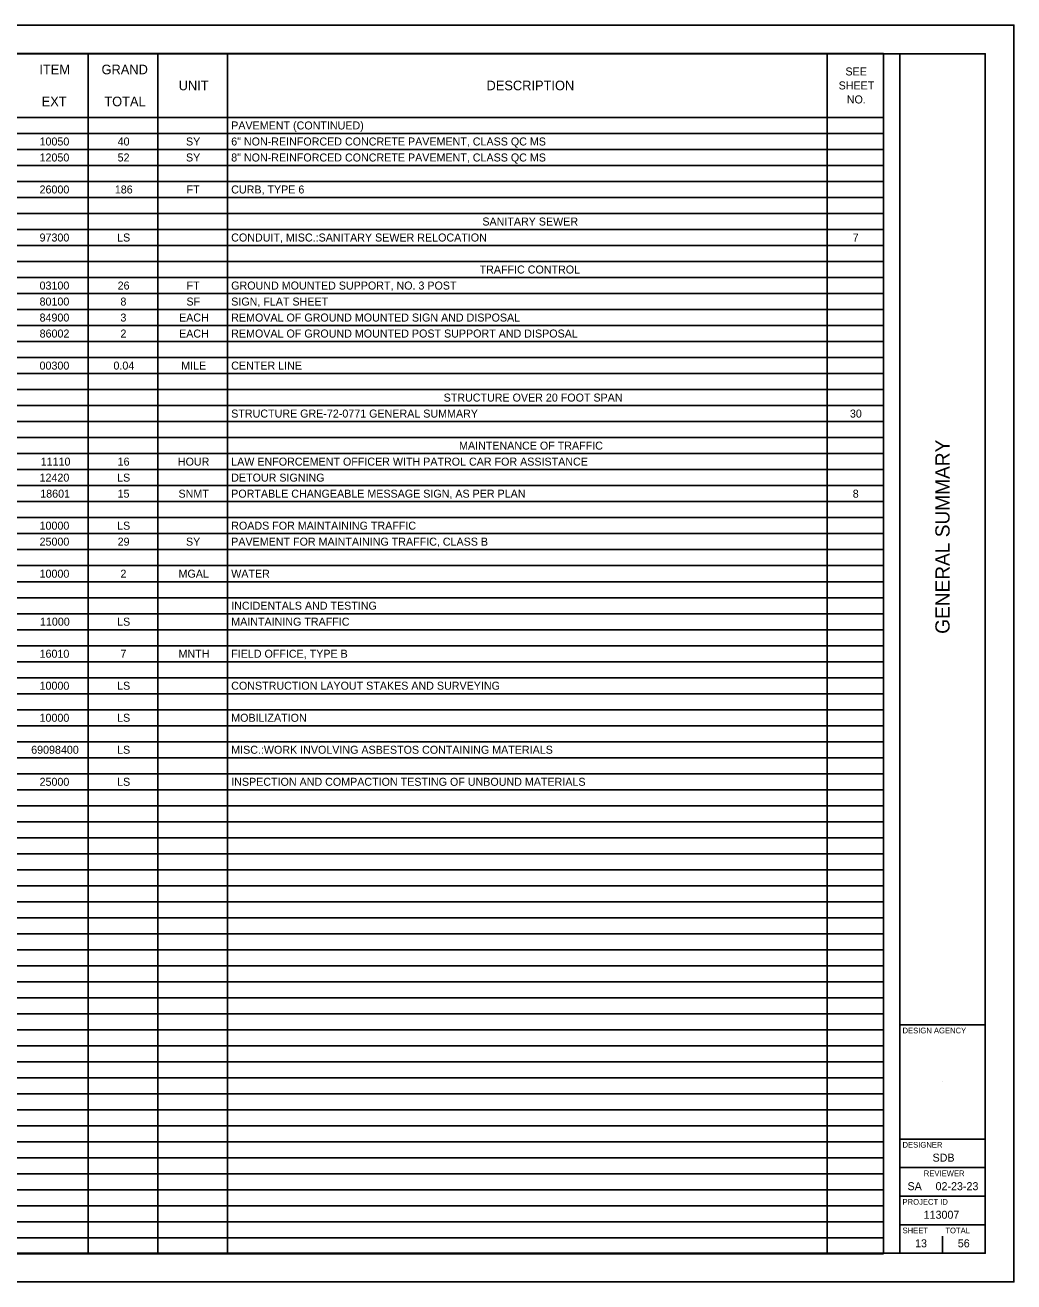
# Model space of a CAD drawing. Extents: x 0 to 34, y 0 to 22.
# Drawn here: x 16.69 to 34, y 0 to 22 of the extents above; entities that cross this region are included whole.
import ezdxf

# ---------------------------------------------------------------- set-up
doc = ezdxf.new("R2010")
doc.units = 0
for name, color, linetype in [('SH_Border', 7, 'Continuous'), ('SH_Cut_Line', 7, 'Continuous'), ('SH_Data', 7, 'Continuous'), ('SH_Text', 7, 'Continuous')]:
    doc.layers.add(name, color=color, linetype=linetype)

msp = doc.modelspace()

# ---------------------------------------------------------------- linework, layer by layer
at = {"layer": 'SH_Border'}
for p, q in [((32, 0.5), (32, 21.5)), ((32, 4.5), (33.5, 4.5)), ((32, 2.5), (33.5, 2.5)), ((32, 2), (33.5, 2)), ((32, 1.5), (33.5, 1.5)), ((32, 1), (33.5, 1))]:
    msp.add_line(p, q, dxfattribs=at)
msp.add_lwpolyline([(1.5, 21.5), (33.5, 21.5), (33.5, 0.5), (1.5, 0.5)], close=True, dxfattribs=at)
at = {"layer": 'SH_Cut_Line'}
msp.add_lwpolyline([(0, 0), (34, 0), (34, 22), (0, 22)], close=True, dxfattribs=at)
at = {"layer": 'SH_Data'}
for p, q in [((32.75, 3.5), (32.75, 3.5)), ((32.375, 0.675), (32.375, 0.675)), ((32.75, 0.5), (32.75, 0.8))]:
    msp.add_line(p, q, dxfattribs=at)
at = {"layer": 'SH_Text'}
for p, q in [((1.503, 21.505), (31.718, 21.505)), ((17.789, 21.505), (17.789, 0.488)), ((19.009, 21.505), (19.009, 0.488)), ((20.228, 21.505), (20.228, 0.488)), ((30.729, 21.505), (30.729, 0.488)), ((31.718, 21.505), (31.718, 0.488)), ((1.503, 20.384), (31.718, 20.384)), ((1.503, 20.104), (31.718, 20.104)), ((1.503, 19.823), (31.718, 19.823)), ((1.503, 19.543), (31.718, 19.543)), ((1.503, 19.263), (31.718, 19.263)), ((1.503, 18.983), (31.718, 18.983)), ((1.503, 18.702), (31.718, 18.702)), ((1.503, 18.422), (31.718, 18.422)), ((1.503, 18.142), (31.718, 18.142)), ((1.503, 17.862), (31.718, 17.862)), ((1.503, 17.582), (31.718, 17.582)), ((1.503, 17.301), (31.718, 17.301)), ((1.503, 17.021), (31.718, 17.021)), ((1.503, 16.741), (31.718, 16.741)), ((1.503, 16.461), (31.718, 16.461)), ((1.503, 16.18), (31.718, 16.18)), ((1.503, 15.9), (31.718, 15.9)), ((1.503, 15.62), (31.718, 15.62)), ((1.503, 15.34), (31.718, 15.34)), ((1.503, 15.06), (31.718, 15.06)), ((1.503, 14.779), (31.718, 14.779)), ((1.503, 14.499), (31.718, 14.499)), ((1.503, 14.219), (31.718, 14.219)), ((1.503, 13.939), (31.718, 13.939)), ((1.503, 13.658), (31.718, 13.658)), ((1.503, 13.378), (31.718, 13.378)), ((1.503, 13.098), (31.718, 13.098)), ((1.503, 12.818), (31.718, 12.818)), ((1.503, 12.538), (31.718, 12.538)), ((1.503, 12.257), (31.718, 12.257)), ((1.503, 11.977), (31.718, 11.977)), ((1.503, 11.697), (31.718, 11.697)), ((1.503, 11.417), (31.718, 11.417)), ((1.503, 11.136), (31.718, 11.136)), ((1.503, 10.856), (31.718, 10.856)), ((1.503, 10.576), (31.718, 10.576)), ((1.503, 10.296), (31.718, 10.296)), ((1.503, 10.016), (31.718, 10.016)), ((1.503, 9.735), (31.718, 9.735)), ((1.503, 9.455), (31.718, 9.455)), ((1.503, 9.175), (31.718, 9.175)), ((1.503, 8.895), (31.718, 8.895)), ((1.503, 8.614), (31.718, 8.614)), ((1.503, 8.334), (31.718, 8.334)), ((1.503, 8.054), (31.718, 8.054)), ((1.503, 7.774), (31.718, 7.774)), ((1.503, 7.494), (31.718, 7.494)), ((1.503, 7.213), (31.718, 7.213)), ((1.503, 6.933), (31.718, 6.933)), ((1.503, 6.653), (31.718, 6.653)), ((1.503, 6.373), (31.718, 6.373)), ((1.503, 6.092), (31.718, 6.092)), ((1.503, 5.812), (31.718, 5.812)), ((1.503, 5.532), (31.718, 5.532)), ((1.503, 5.252), (31.718, 5.252)), ((1.503, 4.972), (31.718, 4.972)), ((1.503, 4.691), (31.718, 4.691)), ((1.503, 4.411), (31.718, 4.411)), ((1.503, 4.131), (31.718, 4.131)), ((1.503, 3.851), (31.718, 3.851)), ((1.503, 3.57), (31.718, 3.57)), ((1.503, 3.29), (31.718, 3.29)), ((1.503, 3.01), (31.718, 3.01)), ((1.503, 2.73), (31.718, 2.73)), ((1.503, 2.45), (31.718, 2.45)), ((1.503, 2.169), (31.718, 2.169)), ((1.503, 1.889), (31.718, 1.889)), ((1.503, 1.609), (31.718, 1.609)), ((1.503, 1.329), (31.718, 1.329)), ((1.503, 1.048), (31.718, 1.048)), ((1.503, 0.768), (31.718, 0.768)), ((1.503, 0.488), (31.718, 0.488))]:
    msp.add_line(p, q, dxfattribs=at)

# ---------------------------------------------------------------- texts
at = {"layer": 'SH_Data'}
msp.add_text('GENERAL SUMMARY', height=0.25, rotation=90, dxfattribs=at).set_placement((32.875, 11.344))
for s, height, p in [('DESIGN AGENCY', 0.1, (32.05, 4.35)), ('DESIGNER', 0.1, (32.05, 2.35)), ('SDB', 0.14, (32.576, 2.105)), ('REVIEWER', 0.1, (32.422, 1.85)), ('SA', 0.14, (32.138, 1.605)), ('02-23-23', 0.14, (32.629, 1.605)), ('PROJECT ID', 0.1, (32.05, 1.35)), ('113007', 0.14, (32.42, 1.105)), ('SHEET', 0.1, (32.05, 0.85)), ('TOTAL', 0.1, (32.8, 0.85)), ('13', 0.14, (32.27, 0.605)), ('56', 0.14, (33.018, 0.605))]:
    msp.add_text(s, height=height, dxfattribs=at).set_placement(p)
at = {"layer": 'SH_Text'}
for s, height, p in [('ITEM', 0.1681, (16.934, 21.14)), ('GRAND', 0.1681, (18.023, 21.14)), ('SEE ', 0.1401, (31.051, 21.119)), ('UNIT', 0.1681, (19.374, 20.86)), ('DESCRIPTION', 0.16814, (24.765, 20.86)), ('SHEET ', 0.1401, (30.931, 20.874)), ('EXT', 0.1681, (16.975, 20.58)), ('TOTAL', 0.1681, (18.072, 20.58)), ('NO.', 0.1401, (31.074, 20.629)), ('PAVEMENT (CONTINUED)', 0.14012, (20.294, 20.174)), ('10050', 0.1401, (16.938, 19.893)), ('40', 0.1401, (18.305, 19.893)), ('SY', 0.1401, (19.502, 19.893)), ('6" NON-REINFORCED CONCRETE PAVEMENT, CLASS QC MS', 0.14012, (20.294, 19.893)), ('12050', 0.1401, (16.938, 19.613)), ('52', 0.1401, (18.305, 19.613)), ('SY', 0.1401, (19.502, 19.613)), ('8" NON-REINFORCED CONCRETE PAVEMENT, CLASS QC MS', 0.14012, (20.294, 19.613)), ('26000', 0.1401, (16.938, 19.053)), ('186', 0.1401, (18.256, 19.053)), ('FT', 0.1401, (19.513, 19.053)), ('CURB, TYPE 6', 0.14012, (20.294, 19.053)), ('SANITARY SEWER', 0.14012, (24.692, 18.492)), ('97300', 0.1401, (16.938, 18.212)), ('LS', 0.1401, (18.296, 18.212)), ('CONDUIT, MISC.:SANITARY SEWER RELOCATION', 0.14012, (20.294, 18.212)), ('7', 0.14, (31.178, 18.212)), ('TRAFFIC CONTROL', 0.14012, (24.644, 17.652)), ('03100', 0.1401, (16.938, 17.371)), ('26', 0.1401, (18.305, 17.371)), ('FT', 0.1401, (19.513, 17.371)), ('GROUND MOUNTED SUPPORT, NO. 3 POST', 0.14012, (20.294, 17.371)), ('80100', 0.1401, (16.938, 17.091)), ('8', 0.14, (18.354, 17.091)), ('SF', 0.1401, (19.51, 17.091)), ('SIGN, FLAT SHEET', 0.14012, (20.294, 17.091)), ('84900', 0.1401, (16.938, 16.811)), ('3', 0.14, (18.354, 16.811)), ('EACH', 0.1401, (19.381, 16.811)), ('REMOVAL OF GROUND MOUNTED SIGN AND DISPOSAL', 0.14012, (20.294, 16.811)), ('86002', 0.1401, (16.939, 16.531)), ('2', 0.14, (18.354, 16.531)), ('EACH', 0.1401, (19.381, 16.531)), ('REMOVAL OF GROUND MOUNTED POST SUPPORT AND DISPOSAL', 0.14012, (20.294, 16.531)), ('00300', 0.1401, (16.938, 15.97)), ('0.04', 0.1401, (18.232, 15.97)), ('MILE', 0.1401, (19.418, 15.97)), ('CENTER LINE', 0.14012, (20.294, 15.97)), ('STRUCTURE OVER 20 FOOT SPAN', 0.14012, (24.014, 15.41)), ('STRUCTURE GRE-72-0771 GENERAL SUMMARY', 0.14012, (20.294, 15.13)), ('30', 0.1401, (31.129, 15.13)), ('MAINTENANCE OF TRAFFIC', 0.14012, (24.284, 14.569)), ('11110', 0.1401, (16.958, 14.289)), ('16', 0.1401, (18.305, 14.289)), ('HOUR', 0.1401, (19.36, 14.289)), ('LAW ENFORCEMENT OFFICER WITH PATROL CAR FOR ASSISTANCE', 0.14012, (20.294, 14.289)), ('12420', 0.1401, (16.938, 14.009)), ('LS', 0.1401, (18.296, 14.009)), ('DETOUR SIGNING', 0.14012, (20.294, 14.009)), ('18601', 0.1401, (16.95, 13.728)), ('15', 0.1401, (18.304, 13.728)), ('SNMT', 0.1401, (19.371, 13.728)), ('PORTABLE CHANGEABLE MESSAGE SIGN, AS PER PLAN', 0.14012, (20.294, 13.728)), ('8', 0.14, (31.178, 13.728)), ('10000', 0.1401, (16.938, 13.168)), ('LS', 0.1401, (18.296, 13.168)), ('ROADS FOR MAINTAINING TRAFFIC', 0.14012, (20.294, 13.168)), ('25000', 0.1401, (16.938, 12.888)), ('29', 0.1401, (18.305, 12.888)), ('SY', 0.1401, (19.502, 12.888)), ('PAVEMENT FOR MAINTAINING TRAFFIC, CLASS B', 0.14012, (20.294, 12.888)), ('10000', 0.1401, (16.938, 12.327)), ('2', 0.14, (18.354, 12.327)), ('MGAL', 0.1401, (19.372, 12.327)), ('WATER', 0.1401, (20.294, 12.327)), ('INCIDENTALS AND TESTING', 0.14012, (20.294, 11.767)), ('11000', 0.1401, (16.945, 11.487)), ('LS', 0.1401, (18.296, 11.487)), ('MAINTAINING TRAFFIC', 0.14012, (20.294, 11.487)), ('16010', 0.1401, (16.938, 10.926)), ('7', 0.14, (18.354, 10.926)), ('MNTH', 0.1401, (19.371, 10.926)), ('FIELD OFFICE, TYPE B', 0.14012, (20.294, 10.926)), ('10000', 0.1401, (16.938, 10.366)), ('LS', 0.1401, (18.296, 10.366)), ('CONSTRUCTION LAYOUT STAKES AND SURVEYING', 0.14012, (20.294, 10.366)), ('10000', 0.1401, (16.938, 9.805)), ('LS', 0.1401, (18.296, 9.805)), ('MOBILIZATION', 0.14012, (20.294, 9.805)), ('69098400', 0.1401, (16.791, 9.245)), ('LS', 0.1401, (18.296, 9.245)), ('MISC.:WORK INVOLVING ASBESTOS CONTAINING MATERIALS', 0.14012, (20.294, 9.245)), ('25000', 0.1401, (16.938, 8.684)), ('LS', 0.1401, (18.296, 8.684)), ('INSPECTION AND COMPACTION TESTING OF UNBOUND MATERIALS', 0.14012, (20.294, 8.684))]:
    msp.add_text(s, height=height, dxfattribs=at).set_placement(p)

doc.saveas('drawing.dxf')
